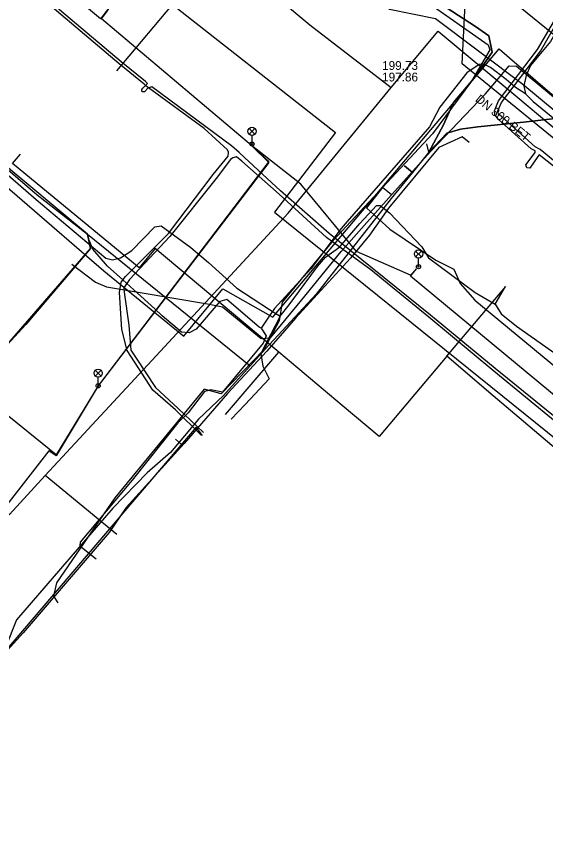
# Model space of a CAD drawing. Extents: x -598932 to -598196, y -1162210 to -1161504.
# Drawn here: x -598521.2 to -598473, y -1161976.1 to -1161902.1 of the extents above; entities that cross this region are included whole.
import ezdxf

# ---------------------------------------------------------------- set-up
doc = ezdxf.new("R2010")
doc.units = 0
for name, color, linetype in [('Vrstva 12', 7, 'Continuous'), ('Vrstva 13', 7, 'Continuous'), ('Vrstva 16', 7, 'Continuous'), ('Vrstva 33', 7, 'Continuous'), ('Vrstva 37', 7, 'Continuous'), ('Vrstva 42', 7, 'Continuous'), ('Vrstva 53', 7, 'Continuous'), ('Vrstva 55', 7, 'Continuous'), ('Vrstva 58', 7, 'Continuous'), ('Vrstva 9', 7, 'Continuous')]:
    doc.layers.add(name, color=color, linetype=linetype)

msp = doc.modelspace()

# ---------------------------------------------------------------- linework, layer by layer
at = {"layer": 'Vrstva 12'}
for p, q in [((-598496.33, -1161928.37), (-598494.97, -1161926.51)), ((-598477.57, -1161928.29), (-598476.63, -1161926.68)), ((-598497.17, -1161929.4), (-598496.33, -1161928.37))]:
    msp.add_line(p, q, dxfattribs=at)
for points in [[(-598530.18, -1161910.6), (-598528.12, -1161912.39), (-598513.23, -1161925.26), (-598505.92, -1161931.22), (-598502.39, -1161926.92), (-598497.84, -1161929.5), (-598487.53, -1161917.27), (-598477.22, -1161905.04), (-598476.26, -1161905.87), (-598456.87, -1161922.52), (-598454.31, -1161925.7), (-598431.25, -1161944.5), (-598424.01, -1161950.11), (-598421.3, -1161953.5), (-598413.48, -1161961.2), (-598396.81, -1161975.36)], [(-598523.15, -1161915.53), (-598519.38, -1161918.78), (-598513.03, -1161924.11), (-598512.44, -1161924.26), (-598511.7, -1161924.07)], [(-598494.97, -1161926.51), (-598493.76, -1161924.86), (-598493.03, -1161924.03), (-598491.73, -1161923.07), (-598489.89, -1161920.94), (-598488.38, -1161919.31), (-598488.04, -1161919.31), (-598487.2, -1161919.98), (-598484.24, -1161923.08), (-598483.64, -1161924.09), (-598479.4, -1161927.24), (-598477.57, -1161928.29)], [(-598511.7, -1161924.07), (-598510.66, -1161923.42), (-598508.57, -1161921.26), (-598507.99, -1161921.16), (-598505.29, -1161923.14), (-598503.7, -1161924.51), (-598501.12, -1161926.83), (-598498.13, -1161928.78), (-598497.17, -1161929.4)], [(-598477.57, -1161928.29), (-598477.02, -1161929.19), (-598475.64, -1161930.32)], [(-598497.17, -1161929.4), (-598498.92, -1161932.8), (-598498.74, -1161933.95), (-598498.16, -1161935.1), (-598500.36, -1161937.44), (-598501.63, -1161938.78)], [(-598475.64, -1161930.32), (-598471.11, -1161933.5), (-598466.42, -1161937.21)]]:
    msp.add_lwpolyline(points, dxfattribs=at)
at = {"layer": 'Vrstva 13'}
for p, q in [((-598521.55, -1161915.5), (-598520.81, -1161914.63)), ((-598481.97, -1161933.05), (-598476.61, -1161926.7)), ((-598502.13, -1161938.35), (-598497.29, -1161932.68)), ((-598477.74, -1161936.64), (-598481.97, -1161933.05)), ((-598470.13, -1161943.11), (-598477.74, -1161936.64))]:
    msp.add_line(p, q, dxfattribs=at)
for points in [[(-598497.29, -1161932.68), (-598508.54, -1161923.23), (-598509.99, -1161925), (-598521.55, -1161915.5)], [(-598481.97, -1161933.05), (-598488.15, -1161940.37), (-598491.52, -1161937.52), (-598497.29, -1161932.68)]]:
    msp.add_lwpolyline(points, dxfattribs=at)
at = {"layer": 'Vrstva 16'}
for p, q in [((-598502.74, -1161895.91), (-598512.06, -1161907.05)), ((-598512.05, -1161949.29), (-598518.56, -1161943.92))]:
    msp.add_line(p, q, dxfattribs=at)
for points in [[(-598592.46, -1161832.67), (-598590.88, -1161833.9), (-598577.93, -1161844.56), (-598562.69, -1161857.12), (-598558.59, -1161860.56), (-598552.71, -1161854.24), (-598543.1, -1161862.22), (-598534.68, -1161869.16), (-598528.87, -1161874.02), (-598515.2, -1161885.47), (-598502.74, -1161895.91), (-598494.45, -1161902.85), (-598487.04, -1161908.55)], [(-598623.45, -1161841.93), (-598614.74, -1161848.93), (-598608.74, -1161854.09), (-598596.77, -1161885.91), (-598521.8, -1161947.46), (-598518.56, -1161943.92), (-598508.46, -1161933.01), (-598496.44, -1161920), (-598487.04, -1161908.55), (-598482.77, -1161903.44), (-598475.7, -1161909.33), (-598469.32, -1161914.66), (-598458.41, -1161923.75), (-598454.13, -1161927.31), (-598447.8, -1161932.54), (-598436.85, -1161941.58), (-598432.08, -1161945.52), (-598424.74, -1161951.46)]]:
    msp.add_lwpolyline(points, dxfattribs=at)
at = {"layer": 'Vrstva 33'}
for p, q in [((-598499.985, -1161912.295), (-598499.455, -1161912.825)), ((-598499.985, -1161912.825), (-598499.455, -1161912.295)), ((-598499.72, -1161913.71), (-598499.72, -1161912.935)), ((-598484.815, -1161923.465), (-598484.285, -1161923.995)), ((-598484.815, -1161923.995), (-598484.285, -1161923.465)), ((-598484.55, -1161924.88), (-598484.55, -1161924.105)), ((-598514.005, -1161934.325), (-598513.475, -1161934.855)), ((-598514.005, -1161934.855), (-598513.475, -1161934.325)), ((-598513.74, -1161935.74), (-598513.74, -1161934.965))]:
    msp.add_line(p, q, dxfattribs=at)
for centre, radius in [((-598499.72, -1161912.56), 0.375), ((-598499.72, -1161913.71), 0.19), ((-598499.72, -1161913.71), 0.05), ((-598484.55, -1161923.73), 0.375), ((-598484.55, -1161924.88), 0.19), ((-598484.55, -1161924.88), 0.05), ((-598513.74, -1161934.59), 0.375), ((-598513.74, -1161935.74), 0.19), ((-598513.74, -1161935.74), 0.05)]:
    msp.add_circle(centre, radius, dxfattribs=at)
at = {"layer": 'Vrstva 37'}
msp.add_lwpolyline([(-598508.056, -1161900.133), (-598492.103, -1161912.672), (-598497.677, -1161919.914), (-598469.69, -1161942.486)], dxfattribs=at)
at = {"layer": 'Vrstva 42'}
for p, q in [((-598483.61, -1161914.46), (-598483.81, -1161913.69)), ((-598485.84, -1161915.7), (-598485.1, -1161916.3)), ((-598504.81, -1161939.5), (-598531.06, -1161970.29)), ((-598504.223, -1161940.263), (-598504.81, -1161939.5)), ((-598506.161, -1161941.084), (-598506.682, -1161940.6))]:
    msp.add_line(p, q, dxfattribs=at)
for points in [[(-598537.93, -1161855.79), (-598533.33, -1161859.23), (-598529.5, -1161862.6), (-598522.43, -1161868.76), (-598516.04, -1161874.11), (-598507.5, -1161881.07), (-598504.93, -1161882.99), (-598502.96, -1161884.74), (-598502.366, -1161885.217), (-598497.689, -1161888.976), (-598494.35, -1161891.66), (-598492.87, -1161892.59), (-598483.08, -1161900.58), (-598479.35, -1161903), (-598478.16, -1161903.85), (-598477.85, -1161905.36), (-598479.52, -1161907.76), (-598480.44, -1161908.82), (-598481.38, -1161909.93), (-598482.29, -1161911.96), (-598483.61, -1161914.46)], [(-598504.347, -1161940.23), (-598506.7, -1161937.92), (-598508.75, -1161936.13), (-598510.43, -1161933.57), (-598511.11, -1161932.53), (-598511.59, -1161930.62), (-598511.79, -1161927.23), (-598511.65, -1161926.31), (-598511.24, -1161925.79), (-598507.34, -1161921.85), (-598503.25, -1161916.5), (-598501.91, -1161914.83), (-598501.86, -1161914.46), (-598501.96, -1161914.24), (-598504.091, -1161912.302), (-598509.141, -1161908.589), (-598509.18, -1161908.56), (-598509.37, -1161908.44), (-598509.423, -1161908.38), (-598509.54, -1161908.25), (-598511.82, -1161906.42), (-598521.08, -1161898.53)], [(-598471.78, -1161938.87), (-598477.58, -1161934.15), (-598483.46, -1161929.29), (-598488.79, -1161925.02), (-598492.7, -1161921.88), (-598497.12, -1161917.97), (-598500.41, -1161914.94), (-598500.88, -1161914.5), (-598501.604, -1161913.875), (-598508.844, -1161908.515), (-598509.037, -1161908.552), (-598509.141, -1161908.589), (-598509.177, -1161908.602), (-598509.502, -1161908.961), (-598509.72, -1161908.949), (-598509.757, -1161908.743), (-598509.657, -1161908.623), (-598509.423, -1161908.38), (-598509.25, -1161908.2), (-598509.44, -1161908.03), (-598511.65, -1161906.22), (-598520.92, -1161898.36)], [(-598468.9, -1161918.4), (-598473.563, -1161914.702), (-598473.691, -1161914.85), (-598474.411, -1161915.919), (-598474.694, -1161915.896), (-598474.767, -1161915.61), (-598473.94, -1161914.48), (-598473.92, -1161914.34), (-598474.28, -1161914.16), (-598477.26, -1161911.49), (-598477.597, -1161911.049), (-598477.63, -1161910.69), (-598477.26, -1161909.77), (-598473.73, -1161905.09), (-598471.95, -1161902.09)], [(-598468.68, -1161918.17), (-598473.46, -1161914.22), (-598473.94, -1161913.97), (-598477.02, -1161911.19), (-598477.27, -1161910.98), (-598477.33, -1161910.68), (-598477.01, -1161909.93), (-598473.45, -1161905.26), (-598471.726, -1161902.24)], [(-598534.52, -1161905.596), (-598528.543, -1161910.378), (-598519.292, -1161918.334), (-598514.716, -1161921.934), (-598514.446, -1161923.219), (-598520.334, -1161930.161), (-598522.35, -1161932.381), (-598524.821, -1161935.027), (-598525.469, -1161935.803), (-598532.131, -1161942.466), (-598533.755, -1161944.184), (-598540.807, -1161952.49), (-598541.148, -1161954.878), (-598537.458, -1161958.679), (-598536.75, -1161959.363), (-598535.647, -1161960.74), (-598534.941, -1161961.517), (-598534.296, -1161961.854), (-598531.569, -1161964.195), (-598534.919, -1161968.016), (-598540.513, -1161974.452), (-598540.611, -1161976.168)], [(-598483.61, -1161914.46), (-598481.98, -1161912.74), (-598480.72, -1161912.35), (-598479.15, -1161912.14), (-598475, -1161911.73), (-598470.01, -1161911.14)], [(-598479.952, -1161913.581), (-598480.58, -1161913.05), (-598482.71, -1161914.04), (-598487.3, -1161919.57), (-598489.02, -1161922.02), (-598490.74, -1161924.1), (-598495.77, -1161929.57), (-598498.36, -1161932.58), (-598501.95, -1161936.45), (-598505.91, -1161941.01), (-598511.18, -1161946.83), (-598512.75, -1161949.09), (-598520.58, -1161958.25), (-598523.46, -1161961.41), (-598526.14, -1161964.7), (-598527.21, -1161965.89), (-598528.4, -1161967.43), (-598531.31, -1161970.76), (-598522.5, -1161978.35), (-598518.45, -1161981.19), (-598513.05, -1161986.47), (-598503.59, -1161988.84), (-598503.97, -1161991.79)], [(-598483.61, -1161914.46), (-598485.1, -1161916.3), (-598487.04, -1161918.68), (-598493.89, -1161927.38), (-598498.51, -1161932.39), (-598502.31, -1161936.61), (-598504.59, -1161938.77), (-598507.15, -1161941.82), (-598509.27, -1161943.67), (-598512.4, -1161946.9), (-598521.17, -1161957.07), (-598522.18, -1161959.57), (-598527.11, -1161965.1), (-598528.1, -1161966.44), (-598530.76, -1161969.59), (-598530.86, -1161970.58), (-598530.01, -1161971.83), (-598527.84, -1161973.27), (-598523.84, -1161976.73), (-598519.92, -1161979.71), (-598515.38, -1161983.85)], [(-598471.92, -1161939.15), (-598477.7, -1161934.4), (-598483.63, -1161929.5), (-598488.89, -1161925.17), (-598492.93, -1161922.23), (-598497.26, -1161918.28), (-598500.64, -1161915.27), (-598501.15, -1161914.89), (-598501.46, -1161914.96), (-598501.68, -1161915.12), (-598502.98, -1161916.84), (-598507.22, -1161922.14), (-598510.88, -1161926.05), (-598511.4, -1161926.81), (-598511.36, -1161927.21), (-598510.94, -1161930.22), (-598510.76, -1161932.5), (-598510.28, -1161933.22), (-598508.52, -1161935.89), (-598506.45, -1161937.8), (-598504.149, -1161939.998)]]:
    msp.add_lwpolyline(points, dxfattribs=at)
at = {"layer": 'Vrstva 53'}
msp.add_line((-598487.007, -1161918.346), (-598487.83, -1161917.67), dxfattribs=at)
for points in [[(-598500.11, -1161887.5), (-598493.43, -1161893.22), (-598484.02, -1161900.57), (-598478.2, -1161904.68), (-598478.06, -1161905.14), (-598479.74, -1161907.98), (-598483.29, -1161912.8), (-598487.83, -1161917.67)], [(-598487.007, -1161918.346), (-598483.42, -1161914.35), (-598478.45, -1161909.14), (-598476.3, -1161906.6), (-598475.63, -1161906.62), (-598462.53, -1161917.47), (-598447.16, -1161930.29), (-598434.4, -1161940.74), (-598425.99, -1161947.45)], [(-598487.83, -1161917.67), (-598492.37, -1161922.53), (-598496.99, -1161928.12), (-598497.25, -1161929.82), (-598498.65, -1161932.46), (-598502.54, -1161936.46), (-598504.09, -1161936.06), (-598512.22, -1161945.93), (-598517.52, -1161953.68), (-598517.8, -1161954.89), (-598517.42, -1161955.5)], [(-598487.83, -1161917.67), (-598489.28, -1161919.53), (-598487.17, -1161921.48), (-598482.98, -1161924.3), (-598481.33, -1161925.12), (-598480.75, -1161926.42), (-598479.43, -1161927.93), (-598468.75, -1161936.76), (-598458, -1161945.63), (-598447.48, -1161954.05), (-598447.47, -1161954.8), (-598448.95, -1161957.4), (-598449.56, -1161958.75), (-598456.47, -1161967.76), (-598467.12, -1161981.29), (-598467.86, -1161982.68), (-598467.93, -1161985.14), (-598467.78, -1161986.21)], [(-598516.15, -1161924.67), (-598513.98, -1161926.29), (-598512.98, -1161926.72), (-598503.78, -1161928.28), (-598502.4, -1161928.56), (-598498.89, -1161931.44), (-598498.03, -1161931.36), (-598495.18, -1161927.92), (-598491.61, -1161923.49), (-598489.75, -1161921.4), (-598487.007, -1161918.346)]]:
    msp.add_lwpolyline(points, dxfattribs=at)
at = {"layer": 'Vrstva 55'}
for points in [[(-598445.98, -1161975.82), (-598420.69, -1161945.55), (-598428.96, -1161939.09), (-598453.01, -1161919.36), (-598497.77, -1161883), (-598523.06, -1161862.52), (-598551.11, -1161839.54), (-598586.36, -1161810.66), (-598588.39, -1161808.928), (-598593.724, -1161815.599)], [(-598499.78, -1161913.86), (-598513.43, -1161902.32), (-598511.45, -1161899.6), (-598513.52, -1161902.32), (-598536.57, -1161883.13), (-598530.17, -1161875.32), (-598558.96, -1161851.14), (-598564.23, -1161856.6), (-598565.08, -1161856.22), (-598564.32, -1161856.69), (-598566.21, -1161858.86), (-598592.74, -1161836.94), (-598590.93, -1161834.32)], [(-598499.78, -1161913.86), (-598498.18, -1161915.4), (-598513.74, -1161935.74), (-598517.57, -1161942.03), (-598538.666, -1161924.967), (-598538.18, -1161924.23), (-598538.666, -1161924.967), (-598558.775, -1161908.38), (-598557.996, -1161907.925), (-598558.775, -1161908.38), (-598578.62, -1161892.07), (-598577.85, -1161891.42), (-598578.62, -1161892.07), (-598598.29, -1161875.42), (-598602.71, -1161872.22), (-598606.57, -1161872.97), (-598620.21, -1161862.81), (-598636.11, -1161882), (-598618.23, -1161860.36)], [(-598499.78, -1161913.86), (-598498.18, -1161915.31), (-598513.74, -1161935.74), (-598517.57, -1161942.12), (-598518.22, -1161941.65), (-598526.88, -1161952.75), (-598539.02, -1161966.87), (-598542.03, -1161968.75), (-598539.02, -1161966.87), (-598536.76, -1161964.14), (-598541.76, -1161959.73), (-598556.121, -1161946.557), (-598556.52, -1161946.95), (-598556.121, -1161946.557), (-598576.128, -1161930.275), (-598576.873, -1161930.758), (-598576.128, -1161930.275), (-598596.85, -1161913.892), (-598597.01, -1161914.27), (-598596.85, -1161913.892), (-598616.857, -1161897.1), (-598617.427, -1161897.6), (-598636.11, -1161882)], [(-598446.033, -1161975.79), (-598445.086, -1161974.588), (-598436.417, -1161966.065), (-598451.7, -1161953.79), (-598450.76, -1161952.48), (-598451.7, -1161953.6), (-598467.14, -1161940.71), (-598466.48, -1161940.05), (-598467.23, -1161940.71), (-598485.3, -1161925.75), (-598484.73, -1161925.09), (-598485.3, -1161925.66), (-598490.19, -1161923.49), (-598495.27, -1161917.38), (-598499.78, -1161913.86)]]:
    msp.add_lwpolyline(points, dxfattribs=at)
at = {"layer": 'Vrstva 58'}
for p, q in [((-598483.61, -1161914.46), (-598485.1, -1161916.3)), ((-598485.84, -1161915.7), (-598485.1, -1161916.3)), ((-598485.1, -1161916.3), (-598485.84, -1161915.7)), ((-598514.716, -1161921.934), (-598499.888, -1161933.921))]:
    msp.add_line(p, q, dxfattribs=at)
for points in [[(-598556.07, -1161844.87), (-598550.13, -1161849.77), (-598546.21, -1161852.92), (-598540.88, -1161857.14), (-598535.48, -1161861.63), (-598530.23, -1161866.04), (-598525.2, -1161870.15), (-598517.44, -1161876.59), (-598511.35, -1161881.71), (-598507.47, -1161884.66), (-598501.04, -1161889.68), (-598494.55, -1161894.93), (-598487.2, -1161901.44), (-598483.01, -1161902.28), (-598475.05, -1161908.26), (-598470.42, -1161912.13)], [(-598479.35, -1161903), (-598483.08, -1161900.58), (-598492.87, -1161892.59), (-598494.35, -1161891.66), (-598497.689, -1161888.976), (-598502.366, -1161885.217), (-598504.93, -1161882.99), (-598507.5, -1161881.07), (-598516.04, -1161874.11), (-598522.43, -1161868.76), (-598529.5, -1161862.6), (-598533.33, -1161859.23), (-598537.93, -1161855.79), (-598544.08, -1161850.56), (-598547.91, -1161847.44), (-598550.17, -1161845.76)], [(-598603.585, -1161846.543), (-598604.434, -1161847.56), (-598602.839, -1161849.016), (-598602.221, -1161849.717), (-598597.187, -1161854.097), (-598591.703, -1161858.144), (-598588.562, -1161861.055), (-598584, -1161864.794), (-598583.326, -1161866.362), (-598583.12, -1161868.355), (-598581.997, -1161871.161), (-598572.083, -1161878.904), (-598562.907, -1161886.163), (-598560.734, -1161887.05), (-598558.231, -1161888.9), (-598549.262, -1161896.79), (-598545.688, -1161899.25), (-598543.156, -1161899.097), (-598541.466, -1161900.059), (-598534.52, -1161905.596), (-598528.543, -1161910.378), (-598519.292, -1161918.334), (-598514.716, -1161921.934)], [(-598537.93, -1161855.79), (-598533.33, -1161859.23), (-598529.5, -1161862.6), (-598522.43, -1161868.76), (-598516.04, -1161874.11), (-598507.5, -1161881.07), (-598504.93, -1161882.99), (-598502.96, -1161884.74), (-598502.366, -1161885.217), (-598497.689, -1161888.976), (-598494.35, -1161891.66), (-598492.87, -1161892.59), (-598483.08, -1161900.58), (-598479.35, -1161903), (-598478.16, -1161903.85), (-598477.85, -1161905.36), (-598479.52, -1161907.76), (-598480.44, -1161908.82), (-598481.38, -1161909.93), (-598482.29, -1161911.96), (-598483.61, -1161914.46)], [(-598483.42, -1161876.6), (-598465.64, -1161891.05), (-598463.79, -1161892.51), (-598463.73, -1161892.75), (-598471.66, -1161902.84), (-598472.18, -1161903.75), (-598472.54, -1161904.36), (-598474.35, -1161906.56), (-598474.76, -1161907.47), (-598474.96, -1161908.4), (-598474.81, -1161909.14)], [(-598483.61, -1161914.46), (-598482.29, -1161911.96), (-598481.38, -1161909.93), (-598479.52, -1161907.76), (-598477.85, -1161905.36), (-598478.16, -1161903.85), (-598479.35, -1161903)], [(-598540.611, -1161976.168), (-598540.513, -1161974.452), (-598534.919, -1161968.016), (-598531.569, -1161964.195), (-598534.296, -1161961.854), (-598534.941, -1161961.517), (-598535.647, -1161960.74), (-598536.75, -1161959.363), (-598537.458, -1161958.679), (-598541.148, -1161954.878), (-598540.807, -1161952.49), (-598533.755, -1161944.184), (-598525.469, -1161935.803), (-598524.821, -1161935.027), (-598522.35, -1161932.381), (-598514.446, -1161923.219), (-598514.716, -1161921.934), (-598528.543, -1161910.378), (-598534.52, -1161905.596)], [(-598474.81, -1161909.14), (-598475.71, -1161908.56), (-598476.57, -1161907.85), (-598478, -1161906.75), (-598478.6, -1161906.43), (-598479.02, -1161906.46), (-598480.14, -1161907.23), (-598482.62, -1161910.37), (-598483.56, -1161912.14), (-598491.05, -1161920.77), (-598491.59, -1161921.42), (-598494.35, -1161925.08), (-598497.66, -1161928.69), (-598498.17, -1161929.39), (-598498.9, -1161930.49)], [(-598474.81, -1161909.14), (-598474.12, -1161909.85), (-598469.35, -1161913.72)], [(-598467.37, -1161912.72), (-598469.17, -1161911.32), (-598470.01, -1161911.14), (-598475, -1161911.73), (-598479.15, -1161912.14), (-598480.72, -1161912.35), (-598481.98, -1161912.74), (-598483.61, -1161914.46)], [(-598483.61, -1161914.46), (-598485.1, -1161916.3), (-598487.04, -1161918.68), (-598493.89, -1161927.38), (-598498.51, -1161932.39), (-598502.31, -1161936.61), (-598504.59, -1161938.77), (-598507.15, -1161941.82), (-598509.27, -1161943.67), (-598512.4, -1161946.9), (-598521.17, -1161957.07), (-598522.18, -1161959.57), (-598527.11, -1161965.1), (-598528.1, -1161966.44), (-598530.76, -1161969.59), (-598530.86, -1161970.58), (-598530.01, -1161971.83), (-598527.84, -1161973.27), (-598523.84, -1161976.73), (-598519.92, -1161979.71), (-598515.38, -1161983.85)], [(-598485.1, -1161916.3), (-598487.04, -1161918.68), (-598493.89, -1161927.38), (-598498.51, -1161932.39), (-598502.31, -1161936.61), (-598504.59, -1161938.77), (-598507.15, -1161941.82), (-598509.27, -1161943.67), (-598512.4, -1161946.9), (-598521.17, -1161957.07), (-598522.18, -1161959.57), (-598527.11, -1161965.1), (-598528.1, -1161966.44)], [(-598498.9, -1161930.49), (-598499.06, -1161930.41), (-598502.01, -1161927.87), (-598502.65, -1161928.06), (-598504.81, -1161930.58), (-598505.45, -1161930.91), (-598506.15, -1161930.85), (-598507.92, -1161929.35), (-598508.59, -1161928.74), (-598510.5, -1161927.01), (-598511.5, -1161926.08), (-598512.88, -1161924.84), (-598514.23, -1161923.3), (-598514.56, -1161922.48)], [(-598498.9, -1161930.49), (-598498.44, -1161931.18), (-598498.71, -1161931.84), (-598502.41, -1161936.31), (-598503.48, -1161936.1), (-598504.06, -1161936.27), (-598505.54, -1161938.19), (-598506.49, -1161939.1), (-598510.65, -1161944.33), (-598515.38, -1161949.98), (-598515.4, -1161950.33), (-598513.93, -1161951.49)]]:
    msp.add_lwpolyline(points, dxfattribs=at)
at = {"layer": 'Vrstva 9'}
for p, q in [((-598480.59, -1161906.42), (-598479.62, -1161888.47)), ((-598445.71, -1161934.82), (-598480.59, -1161906.42))]:
    msp.add_line(p, q, dxfattribs=at)

# ---------------------------------------------------------------- texts
at = {"layer": 'Vrstva 12'}
for s, p in [('199.73', (-598487.873, -1161906.963)), ('197.86', (-598487.873, -1161908.013))]:
    msp.add_text(s, height=0.8, dxfattribs=at).set_placement(p)
msp.add_text('DN 300 BET', height=0.8, rotation=321, dxfattribs=at).set_placement((-598479.446, -1161909.755))

doc.saveas('drawing.dxf')
